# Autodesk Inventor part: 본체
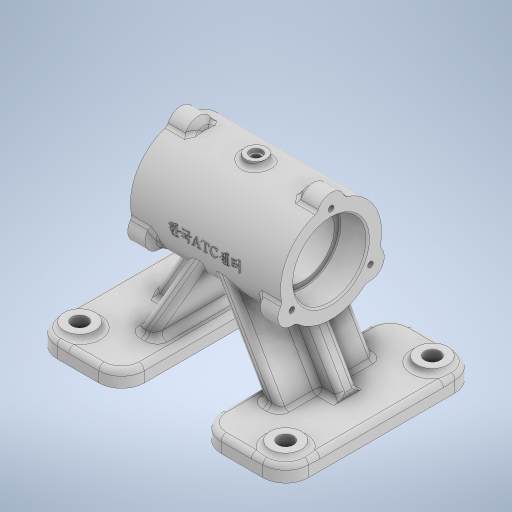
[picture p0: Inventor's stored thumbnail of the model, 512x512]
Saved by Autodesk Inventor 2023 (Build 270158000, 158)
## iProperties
Created: 2026-04
Part Number: 본체
Material: 일반
Document SubType Name: Modeling
Designer: home
Density: 1 g/cm^3
Appearance: 기본값
Author: home
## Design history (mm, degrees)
sketch "스케치1"
  geometry: L1 (-26.777, 0)-(26.777, 0); L2 (0, 0)-(0, 31.451); L3 (-26.777, 72)-(26.777, 72); L4 (-43, 72)-(-43, 101); L5 (-43, 101)-(43, 101); L6 (-43, 93)-(-27, 93); L7 (-27, 93)-(-27, 90); L8 (-27, 90)-(27, 90); L9 (27, 90)-(27, 93); L10 (27, 93)-(43, 93); L11 (43, 101)-(43, 72); 3 further points
  constraints: 22 end point, 5 point on line, 4 perpendicular, 3 horizontal, 3 midpoint, 2 vertical, 2 vertical alignment, 1 coincident, 1 parallel
  dimensions: "d0" = 72 distance from line of point (0, 0) L3; "d1" = 86 distance of L4.end L5.end; "d2" = 42 diameter of L6 L3; "d3" = 58 diameter of L5 L3; "d4" = 36 diameter of L8 L3; "d5" = 16 distance of L6.start L6.end; "d6" = 16 distance of L9.end L10.end
revolve "회전1" sketch "스케치1" stored, may be unused: angle "d7" = 90 deg
sketch "스케치2"
  geometry: L1 (-72.382, 0)-(72.382, 0); L2 (-72.382, -72)-(72.382, -72); L3 (0, 0)-(0, 26); C1 r 34 at (0, 0); C2 r 26 at (0, 0); A1 r 29 centre (0, 0) between (7.761, 27.942) and (-7.761, 27.942) reference; A2 r 8 centre (0, 26) between (7.761, 27.942) and (-7.761, 27.942); A3 r 29 centre (0, 0) between (7.761, 27.942) and (-7.761, 27.942); A4 r 29 centre (0, 0) between (-29, 0) and (29, 0); 4 further points
  constraints: 9 point on circle, 6 end point, 5 centre point, 5 coincident, 2 midpoint, 2 point on line, 1 horizontal, 1 parallel, 1 vertical
  dimensions: "d8" = 72 distance between parallel lines of L1 L2; "d10" = 68 diameter of C1; "d11" = 106 distance of point (0, -72) point (0, 34); "d12" = 52 diameter of C2; "d13" = 26 distance of L3.start L3.end; "d14" = 8 radius of A2
extrude "돌출1" join sketch "스케치2" distance "d15" = 14; taper "d16" = 0 deg
sketch "스케치9"
  geometry: L1 (59, -55)-(35, -55); L2 (22, -42)-(22, 42); L3 (35, 55)-(59, 55); L4 (72, 42)-(72, -42); A1 r 13 centre (59, -42) between (59, -55) and (72, -42); A2 r 13 centre (59, 42) between (72, 42) and (59, 55); A3 r 13 centre (35, 42) between (35, 55) and (22, 42); A4 r 13 centre (35, -42) between (22, -42) and (35, -55); 5 further points
  constraints: 8 end point, 8 point on circle, 8 tangent, 6 point on line, 4 centre point, 3 equal radius, 2 parallel, 1 horizontal, 1 horizontal alignment, 1 midpoint, 1 perpendicular
  dimensions: "d56" = 50 distance of point (72, -55) point (22, -55); "d57" = 110 distance of point (72, 55) point (72, -55); "d58" = 22 distance from line of point (0, 0) L2; "d59" = 13 radius of A1
extrude "돌출4" join sketch "스케치9" distance "d60" = 9; taper "d61" = 0 deg
sketch "스케치10"
  geometry: C1 r 9 at (-59, 42); C2 r 9 at (-59, -42); 1 further point
  constraints: 2 centre point, 1 vertical alignment
  dimensions: "d62" = 18 diameter of C1; "d63" = 18 diameter of C2; "d64" = 42 vertical distance of point (0, 0) C1.centre; "d65" = 42 vertical distance of C2.centre point (0, 0); "d66" = 59 horizontal distance of point (0, 0) C1.centre
extrude "돌출5" join sketch "스케치10" distance "d67" = 3; taper "d68" = 0 deg
fillet "모깎기5" dims "d69" = 3
sketch "스케치11"
  geometry: C1 r 9 at (0, 0) reference; C2 r 9 at (0, -84) reference; 3 further points
  constraints: 2 coincident
hole "구멍3" sketch "스케치11" at (0, 0), (0, -84) diameter "d70" = 9; stored, may be unused: countersink angle "d74" = 90 deg, drill point angle "d76" = 118 deg; dims "d71" = 6, "d72" = 4, "d73" = 2, "d75" = 8
node "작업 평면4"
sketch "스케치12"
  geometry: C1 r 6 at (0, 0); 1 further point
  constraints: 1 centre point, 1 coincident
  dimensions: "d78" = 12 diameter of C1
extrude "돌출6" join sketch "스케치12" stored distance "d79" = 3; taper "d80" = 0 deg
sketch "스케치13"
  geometry: C1 r 6 at (0, 0) reference; 2 further points
  constraints: 1 coincident
hole "구멍4" sketch "스케치13" at (0, 0) diameter "d81" = 4.917; stored, may be unused: countersink angle "d85" = 90 deg, drill point angle "d87" = 118 deg; dims "d82" = 12, "d83" = 7, "d84" = 2, "d86" = 8
node "작업 평면5"
sketch "스케치15"
  geometry: L1 (12.37, 43)-(32, 9); L2 (22, 0)-(22, 6) reference; L3 (-43, 43)-(43, 43) reference; L4 (21.608, 43)-(41.238, 9); L5 (35, 9)-(25, 9) reference; L6 (52.367, 9)-(35, 9) reference; L7 (32, 9)-(41.238, 9); 1 further point
  constraints: 6 end point, 4 point on line, 1 horizontal, 1 parallel
  dimensions: "d99" = 10 distance from line of L2 L1.end; "d100" = 30 deg angle of L2 L1; "d101" = 8 distance between parallel lines of L1 L4
feature "리브2" sketch "스케치15" dims "d102" = 1, "d103" = 54, "d104" = 0, "d105" = 0, "d106" = 1, "d107" = 1
sketch "스케치17"
  geometry: L1 (10.975, 61.417)-(41.238, 9) reference; L2 (35.464, 43)-(55.051, 9.075); L3 (35, 9)-(52.367, 9) reference; L4 (70, 9.172)-(59, 9.172) reference; L5 (-43, 43)-(43, 43) reference; 2 further points
  constraints: 2 end point, 1 parallel, 1 point on line, 2 other
  dimensions: "d116" = 12 distance between parallel lines of L1 L2
extrude "돌출7" join sketch "스케치17" stored distance "d117" = 10; taper "d118" = 0 deg
sketch "스케치18"
  geometry: L1 (0, -26)-(0, 0); C1 r 21 at (0, -26) reference; 1 further point
  constraints: 2 end point, 1 vertical
  dimensions: "d119" = 26 distance of L1.start L1.end
hole "구멍5" sketch "스케치18" at (0, 0) diameter "d120" = 3.242; stored, may be unused: countersink angle "d124" = 90 deg, drill point angle "d126" = 118 deg; dims "d121" = 8, "d122" = 7, "d123" = 2, "d125" = 10
chamfer "모따기1" distance "d130" = 4; stored, may be unused: second distance "d131" = 2, angle "d132" = 45 deg
sketch "스케치19"
  geometry: 1 further point
fillet "모깎기6" dims "d133" = 3
fillet "모깎기7" dims "d134" = 0.6
chamfer "모따기2" distance "d135" = 1; stored, may be unused: second distance "d136" = 2, angle "d137" = 45 deg
fillet "모깎기8" dims "d138" = 3
fillet "모깎기9" dims "d139" = 3
fillet "모깎기10" dims "d140" = 3
node "작업 평면6"
sketch "스케치20"
  geometry: L1 (-22.752, 91.294)-(22.752, 91.294); L2 (22.752, 91.294)-(22.752, 52.706); L3 (22.752, 52.706)-(-22.752, 52.706); L4 (-22.752, 52.706)-(-22.752, 91.294); 3 further points
  constraints: 2 midpoint, 1 vertical alignment, 2 other
  dimensions: "d142" = 72 vertical distance of point (0, 0) point (22.752, 72)
feature "엠보싱1" sketch "스케치20" dims "d0" = 72, "d1" = 86, "d2" = 42, "d3" = 58, "d4" = 36, "d5" = 16, "d6" = 16, "d8" = 72, "d10" = 68, "d11" = 106, "d12" = 52, "d13" = 26, "d14" = 8, "d143" = 0.5, "d144" = 0
node "솔리드1"
pattern_circular "원형 패턴1" dims angle "d18" = 360 deg
mirror "미러1"
mirror "미러3"
mirror "미러4"
mirror "미러5"
pattern_circular "원형 패턴2" dims angle "d128" = 360 deg
mirror "미러6"
feature "A9D066F2-1C7D-4E18-AEED-F7BC21143FA4" dims "d70" = 9, "d71" = 6, "d72" = 4, "d73" = 2, "d74" = 90 deg, "d75" = 8, "d76" = 118 deg
other parameters: "d77" = 104, "d88" = 72, "d141" = 37
